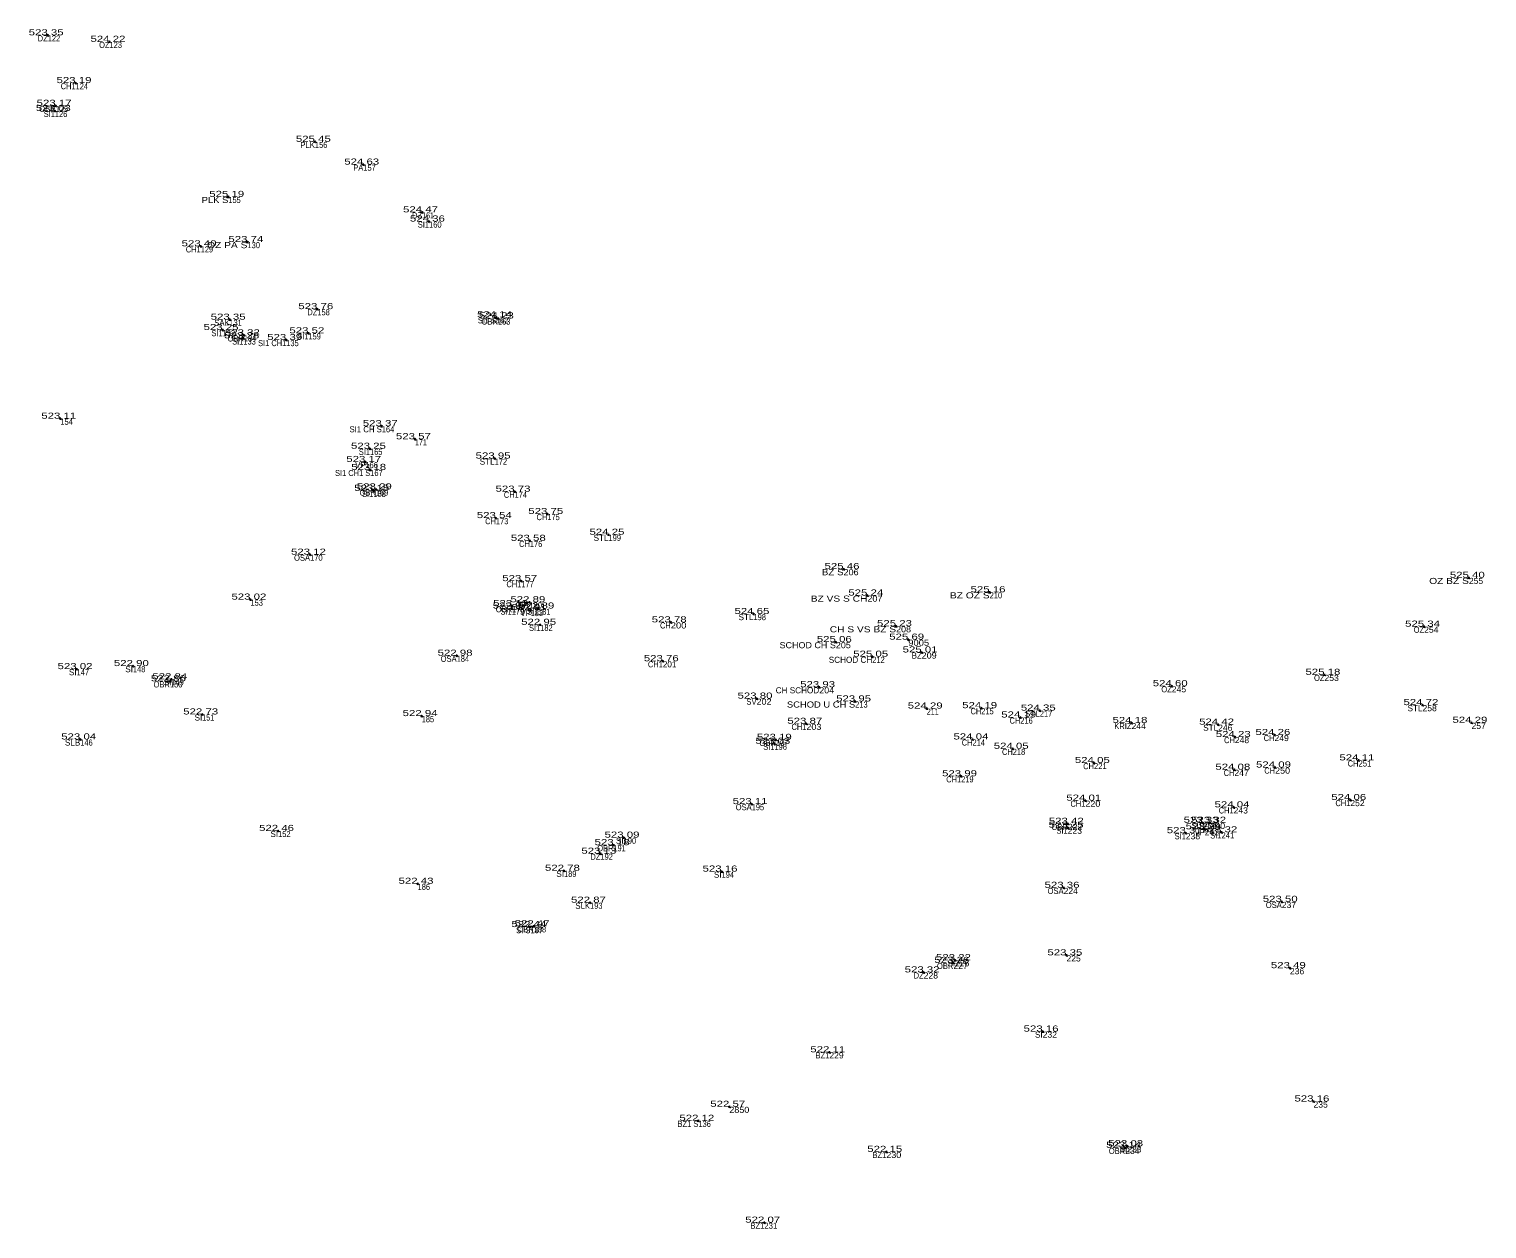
# Model space of a CAD drawing. Extents: x -643086 to -639283, y -1131805 to -1123269.
# Drawn here: x -641269.1 to -641197.4, y -1126078.8 to -1126019.7 of the extents above; entities that cross this region are included whole.
import ezdxf
from ezdxf.enums import TextEntityAlignment as Align

# ---------------------------------------------------------------- set-up
doc = ezdxf.new("R2010")
doc.units = 0
doc.header["$LTSCALE"] = 0.12
doc.header["$PDMODE"] = 32
doc.header["$PDSIZE"] = 0.06
for name, color, linetype in [('1', 7, 'Continuous'), ('2', 7, 'Continuous'), ('3', 7, 'Continuous'), ('4', 7, 'Continuous')]:
    doc.layers.add(name, color=color, linetype=linetype)

msp = doc.modelspace()

# ---------------------------------------------------------------- linework, layer by layer
at = {"layer": '1'}
for p in [(-641268.19, -1126020.04), (-641265.15, -1126020.36), (-641266.82, -1126022.39), (-641267.8, -1126023.51), (-641267.84, -1126023.76), (-641255.05, -1126025.28), (-641252.67, -1126026.4), (-641259.31, -1126027.99), (-641249.78, -1126028.75), (-641249.44, -1126029.2), (-641260.67, -1126030.42), (-641258.37, -1126030.21), (-641254.93, -1126033.51), (-641259.24, -1126034.03), (-641246.14, -1126033.91), (-641246.05, -1126033.97), (-641259.59, -1126034.54), (-641258.57, -1126034.95), (-641258.54, -1126034.8), (-641255.37, -1126034.7), (-641256.46, -1126035.03), (-641267.57, -1126038.9), (-641251.76, -1126039.27), (-641250.13, -1126039.91), (-641252.34, -1126040.38), (-641252.57, -1126041.03), (-641252.33, -1126041.42), (-641246.21, -1126040.86), (-641252.18, -1126042.45), (-641252.05, -1126042.38), (-641245.23, -1126042.49), (-641243.62, -1126043.59), (-641246.15, -1126043.79), (-641244.48, -1126044.91), (-641240.61, -1126044.61), (-641255.29, -1126045.59), (-641229.05, -1126046.3), (-641244.9, -1126046.89), (-641198.3, -1126046.73), (-641258.22, -1126047.8), (-641227.88, -1126047.6), (-641221.87, -1126047.44), (-641245.37, -1126048.24), (-641245.35, -1126048.12), (-641244.5, -1126047.93), (-641244.44, -1126048.31), (-641244.06, -1126048.24), (-641233.48, -1126048.51), (-641243.97, -1126049.04), (-641237.55, -1126048.92), (-641226.47, -1126049.11), (-641200.5, -1126049.13), (-641229.43, -1126049.89), (-641225.87, -1126049.77), (-641248.08, -1126050.56), (-641227.64, -1126050.61), (-641225.21, -1126050.4), (-641266.77, -1126051.22), (-641264, -1126051.07), (-641237.94, -1126050.83), (-641205.4, -1126051.5), (-641262.18, -1126051.82), (-641262.11, -1126051.72), (-641230.25, -1126052.11), (-641212.91, -1126052.06), (-641233.33, -1126052.67), (-641228.48, -1126052.81), (-641260.59, -1126053.45), (-641249.8, -1126053.53), (-641224.96, -1126053.16), (-641222.28, -1126053.14), (-641220.36, -1126053.6), (-641219.4, -1126053.26), (-641200.58, -1126052.99), (-641230.88, -1126053.91), (-641214.89, -1126053.87), (-641210.63, -1126053.95), (-641198.17, -1126053.86), (-641266.59, -1126054.68), (-641232.45, -1126054.89), (-641232.38, -1126054.7), (-641222.71, -1126054.68), (-641209.81, -1126054.56), (-641207.86, -1126054.46), (-641220.73, -1126055.14), (-641203.73, -1126055.71), (-641223.27, -1126056.49), (-641216.74, -1126055.84), (-641209.83, -1126056.17), (-641207.83, -1126056.06), (-641233.57, -1126057.86), (-641217.16, -1126057.69), (-641204.13, -1126057.66), (-641209.87, -1126058.02), (-641256.86, -1126059.18), (-641218.03, -1126059.02), (-641218.02, -1126058.83), (-641212.22, -1126059.29), (-641211.39, -1126058.78), (-641211.29, -1126059.1), (-641211.02, -1126058.78), (-641210.47, -1126059.25), (-641240.36, -1126059.88), (-641239.87, -1126059.51), (-641241.01, -1126060.3), (-641242.8, -1126061.14), (-641235.05, -1126061.18), (-641250, -1126061.78), (-641218.23, -1126061.98), (-641241.52, -1126062.71), (-641207.5, -1126062.67), (-641244.45, -1126063.91), (-641244.29, -1126063.87), (-641223.65, -1126065.67), (-641223.57, -1126065.54), (-641218.09, -1126065.3), (-641225.11, -1126066.14), (-641207.1, -1126065.93), (-641219.26, -1126069.05), (-641229.75, -1126070.07), (-641234.67, -1126072.75), (-641205.94, -1126072.49), (-641236.19, -1126073.44), (-641226.95, -1126074.97), (-641215.2, -1126074.77), (-641215.1, -1126074.69), (-641232.95, -1126078.45)]:
    msp.add_point(p, dxfattribs=at)

# ---------------------------------------------------------------- texts
at = {"layer": '2'}
for s, width, p in [('122', 0.8, (-641268.19, -1126020.34)), ('123', 0.8, (-641265.15, -1126020.66)), ('124', 0.8, (-641266.82, -1126022.69)), ('125', 0.8, (-641267.8, -1126023.81)), ('126', 0.8, (-641267.84, -1126024.06)), ('156', 0.8, (-641255.05, -1126025.58)), ('157', 0.8, (-641252.67, -1126026.7)), ('155', 0.8, (-641259.31, -1126028.29)), ('161', 0.7, (-641249.78, -1126029.05)), ('160', 0.85, (-641249.44, -1126029.5)), ('129', 0.8, (-641260.67, -1126030.72)), ('130', 0.85, (-641258.37, -1126030.51)), ('158', 0.8, (-641254.93, -1126033.81)), ('131', 0.7, (-641259.24, -1126034.33)), ('162', 0.8, (-641246.14, -1126034.21)), ('163', 0.8, (-641246.05, -1126034.27)), ('132', 0.8, (-641259.59, -1126034.84)), ('133', 0.8, (-641258.57, -1126035.25)), ('134', 0.8, (-641258.54, -1126035.1)), ('159', 0.8, (-641255.37, -1126035)), ('135', 0.8, (-641256.46, -1126035.33)), ('154', 0.8, (-641267.57, -1126039.2)), ('164', 0.8, (-641251.76, -1126039.57)), ('171', 0.7, (-641250.13, -1126040.21)), ('165', 0.8, (-641252.34, -1126040.68)), ('166', 0.85, (-641252.57, -1126041.33)), ('167', 0.8, (-641252.33, -1126041.72)), ('172', 0.8, (-641246.21, -1126041.16)), ('168', 0.8, (-641252.18, -1126042.75)), ('169', 0.8, (-641252.05, -1126042.68)), ('174', 0.8, (-641245.23, -1126042.79)), ('175', 0.8, (-641243.62, -1126043.89)), ('173', 0.8, (-641246.15, -1126044.09)), ('176', 0.8, (-641244.48, -1126045.21)), ('199', 0.8, (-641240.61, -1126044.91)), ('170', 0.85, (-641255.29, -1126045.89)), ('206', 1.1, (-641229.05, -1126046.6)), ('177', 0.8, (-641244.9, -1126047.19)), ('255', 1.05, (-641198.3, -1126047.03)), ('153', 0.8, (-641258.22, -1126048.1)), ('207', 1.1, (-641227.88, -1126047.9)), ('210', 0.85, (-641221.87, -1126047.74)), ('179', 0.8, (-641245.37, -1126048.54)), ('178', 0.8, (-641245.35, -1126048.42)), ('180', 0.85, (-641244.5, -1126048.23)), ('183', 0.8, (-641244.44, -1126048.61)), ('181', 0.7, (-641244.06, -1126048.54)), ('198', 0.8, (-641233.48, -1126048.81)), ('182', 0.8, (-641243.97, -1126049.34)), ('200', 1.15, (-641237.55, -1126049.22)), ('208', 1.1, (-641226.47, -1126049.41)), ('254', 1.05, (-641200.5, -1126049.43)), ('205', 1.1, (-641229.43, -1126050.19)), ('9005', 1.15, (-641225.87, -1126050.07)), ('184', 0.8, (-641248.08, -1126050.86)), ('212', 0.8, (-641227.64, -1126050.91)), ('209', 1.1, (-641225.21, -1126050.7)), ('147', 0.8, (-641266.77, -1126051.52)), ('148', 0.8, (-641264, -1126051.37)), ('150', 0.85, (-641262.18, -1126052.12)), ('149', 0.8, (-641262.11, -1126052.02)), ('204', 1.1, (-641230.25, -1126052.41)), ('245', 1.05, (-641212.91, -1126052.36)), ('253', 1.05, (-641205.4, -1126051.8)), ('202', 1.1, (-641233.33, -1126052.97)), ('213', 0.8, (-641228.48, -1126053.11)), ('151', 0.7, (-641260.59, -1126053.75)), ('185', 0.8, (-641249.8, -1126053.83)), ('211', 0.7, (-641224.96, -1126053.46)), ('215', 0.8, (-641222.28, -1126053.44)), ('216', 0.8, (-641220.36, -1126053.9)), ('217', 0.8, (-641219.4, -1126053.56)), ('258', 1.05, (-641200.58, -1126053.29)), ('203', 1.1, (-641230.88, -1126054.21)), ('244', 1.05, (-641214.89, -1126054.17)), ('246', 1.05, (-641210.63, -1126054.25)), ('257', 1.05, (-641198.17, -1126054.16)), ('146', 0.8, (-641266.59, -1126054.98)), ('196', 0.8, (-641232.45, -1126055.19)), ('197', 0.8, (-641232.38, -1126055)), ('214', 0.8, (-641222.71, -1126054.98)), ('248', 1.05, (-641209.81, -1126054.86)), ('249', 1.05, (-641207.86, -1126054.76)), ('218', 0.8, (-641220.73, -1126055.44)), ('251', 0.95, (-641203.73, -1126056.01)), ('219', 0.8, (-641223.27, -1126056.79)), ('221', 0.95, (-641216.74, -1126056.14)), ('247', 1.05, (-641209.83, -1126056.47)), ('250', 1.1, (-641207.83, -1126056.36)), ('195', 0.8, (-641233.57, -1126058.16)), ('220', 1.1, (-641217.16, -1126057.99)), ('252', 1.05, (-641204.13, -1126057.96)), ('243', 1.05, (-641209.87, -1126058.32)), ('152', 0.8, (-641256.86, -1126059.48)), ('223', 1.05, (-641218.03, -1126059.32)), ('222', 1.05, (-641218.02, -1126059.13)), ('238', 1.05, (-641212.22, -1126059.59)), ('239', 1.05, (-641211.39, -1126059.08)), ('242', 1.05, (-641211.29, -1126059.4)), ('240', 1.1, (-641211.02, -1126059.08)), ('241', 0.95, (-641210.47, -1126059.55)), ('191', 0.7, (-641240.36, -1126060.18)), ('190', 0.85, (-641239.87, -1126059.81)), ('192', 0.8, (-641241.01, -1126060.6)), ('189', 0.8, (-641242.8, -1126061.44)), ('194', 0.8, (-641235.05, -1126061.48)), ('186', 0.8, (-641250, -1126062.08)), ('224', 1.05, (-641218.23, -1126062.28)), ('193', 0.8, (-641241.52, -1126063.01)), ('237', 1.05, (-641207.5, -1126062.97)), ('187', 0.8, (-641244.45, -1126064.21)), ('188', 0.8, (-641244.29, -1126064.17)), ('227', 1.05, (-641223.65, -1126065.97)), ('226', 1.05, (-641223.57, -1126065.84)), ('225', 1.05, (-641218.09, -1126065.6)), ('228', 1.05, (-641225.11, -1126066.44)), ('236', 1.05, (-641207.1, -1126066.23)), ('232', 1.05, (-641219.26, -1126069.35)), ('229', 1.05, (-641229.75, -1126070.37)), ('2850', 1.1, (-641234.67, -1126073.05)), ('235', 1.05, (-641205.94, -1126072.79)), ('136', 0.8, (-641236.19, -1126073.74)), ('230', 1.1, (-641226.95, -1126075.27)), ('234', 1.05, (-641215.2, -1126075.07)), ('233', 1.05, (-641215.1, -1126074.99)), ('231', 0.95, (-641232.95, -1126078.75))]:
    msp.add_text(s, height=0.3, dxfattribs=dict(at, width=width)).set_placement(p)
msp.add_text('201', height=0.3, dxfattribs=at).set_placement((-641237.94, -1126051.13))
at = {"layer": '3', "width": 1.4}
for s, p in [('523 35 ', (-641268.19, -1126020.04)), ('524 22 ', (-641265.15, -1126020.36)), ('523 19 ', (-641266.82, -1126022.39)), ('523 03 ', (-641267.84, -1126023.76)), ('523 17 ', (-641267.8, -1126023.51)), ('525 45 ', (-641255.05, -1126025.28)), ('524 63 ', (-641252.67, -1126026.4)), ('525 19 ', (-641259.31, -1126027.99)), ('524 47 ', (-641249.78, -1126028.75)), ('524 36 ', (-641249.44, -1126029.2)), ('523 74 ', (-641258.37, -1126030.21)), ('523 40 ', (-641260.67, -1126030.42)), ('523 76 ', (-641254.93, -1126033.51)), ('523 25 ', (-641259.59, -1126034.54)), ('523 35 ', (-641259.24, -1126034.03)), ('524 14 ', (-641246.14, -1126033.91)), ('524 23 ', (-641246.05, -1126033.97)), ('523 28 ', (-641258.57, -1126034.95)), ('523 32 ', (-641258.54, -1126034.8)), ('523 39 ', (-641256.46, -1126035.03)), ('523 52 ', (-641255.37, -1126034.7)), ('523 11 ', (-641267.57, -1126038.9)), ('523 37 ', (-641251.76, -1126039.27)), ('523 57 ', (-641250.13, -1126039.91)), ('523 17 ', (-641252.57, -1126041.03)), ('523 25 ', (-641252.34, -1126040.38)), ('523 95 ', (-641246.21, -1126040.86)), ('523 18 ', (-641252.33, -1126041.42)), ('523 15 ', (-641252.18, -1126042.45)), ('523 29 ', (-641252.05, -1126042.38)), ('523 73 ', (-641245.23, -1126042.49)), ('523 54 ', (-641246.15, -1126043.79)), ('523 75 ', (-641243.62, -1126043.59)), ('524 25 ', (-641240.61, -1126044.61)), ('523 58 ', (-641244.48, -1126044.91)), ('523 12 ', (-641255.29, -1126045.59)), ('525 46 ', (-641229.05, -1126046.3)), ('525 40 ', (-641198.3, -1126046.73)), ('523 57 ', (-641244.9, -1126046.89)), ('525 16 ', (-641221.87, -1126047.44)), ('523 02 ', (-641258.22, -1126047.8)), ('523 12 ', (-641245.35, -1126048.12)), ('522 89 ', (-641244.5, -1126047.93)), ('525 24 ', (-641227.88, -1126047.6)), ('522 97 ', (-641245.37, -1126048.24)), ('522 91 ', (-641244.44, -1126048.31)), ('522 89 ', (-641244.06, -1126048.24)), ('524 65 ', (-641233.48, -1126048.51)), ('522 95 ', (-641243.97, -1126049.04)), ('523 78 ', (-641237.55, -1126048.92)), ('525 23 ', (-641226.47, -1126049.11)), ('525 34 ', (-641200.5, -1126049.13)), ('525 06 ', (-641229.43, -1126049.89)), ('525 69 ', (-641225.87, -1126049.77)), ('522 98 ', (-641248.08, -1126050.56)), ('523 76 ', (-641237.94, -1126050.83)), ('525 05 ', (-641227.64, -1126050.61)), ('525 01 ', (-641225.21, -1126050.4)), ('523 02 ', (-641266.77, -1126051.22)), ('522 90 ', (-641264, -1126051.07)), ('522 84 ', (-641262.11, -1126051.72)), ('525 18 ', (-641205.4, -1126051.5)), ('522 86 ', (-641262.18, -1126051.82)), ('523 93 ', (-641230.25, -1126052.11)), ('524 60 ', (-641212.91, -1126052.06)), ('523 80 ', (-641233.33, -1126052.67)), ('523 95 ', (-641228.48, -1126052.81)), ('524 29 ', (-641224.96, -1126053.16)), ('524 19 ', (-641222.28, -1126053.14)), ('524 72 ', (-641200.58, -1126052.99)), ('522 73 ', (-641260.59, -1126053.45)), ('522 94 ', (-641249.8, -1126053.53)), ('523 87 ', (-641230.88, -1126053.91)), ('524 19 ', (-641220.36, -1126053.6)), ('524 35 ', (-641219.4, -1126053.26)), ('524 18 ', (-641214.89, -1126053.87)), ('524 29 ', (-641198.17, -1126053.86)), ('524 42 ', (-641210.63, -1126053.95)), ('524 23 ', (-641209.81, -1126054.56)), ('524 26 ', (-641207.86, -1126054.46)), ('523 04 ', (-641266.59, -1126054.68)), ('523 03 ', (-641232.45, -1126054.89)), ('523 19 ', (-641232.38, -1126054.7)), ('524 04 ', (-641222.71, -1126054.68)), ('524 05 ', (-641220.73, -1126055.14)), ('524 05 ', (-641216.74, -1126055.84)), ('524 09 ', (-641207.83, -1126056.06)), ('524 11 ', (-641203.73, -1126055.71)), ('523 99 ', (-641223.27, -1126056.49)), ('524 08 ', (-641209.83, -1126056.17)), ('523 11 ', (-641233.57, -1126057.86)), ('524 01 ', (-641217.16, -1126057.69)), ('524 04 ', (-641209.87, -1126058.02)), ('524 06 ', (-641204.13, -1126057.66)), ('523 42 ', (-641218.02, -1126058.83)), ('523 33 ', (-641211.39, -1126058.78)), ('523 32 ', (-641211.02, -1126058.78)), ('522 46 ', (-641256.86, -1126059.18)), ('523 09 ', (-641239.87, -1126059.51)), ('523 25 ', (-641218.03, -1126059.02)), ('523 31 ', (-641212.22, -1126059.29)), ('523 29 ', (-641211.29, -1126059.1)), ('523 32 ', (-641210.47, -1126059.25)), ('523 13 ', (-641241.01, -1126060.3)), ('523 18 ', (-641240.36, -1126059.88)), ('522 43 ', (-641250, -1126061.78)), ('522 78 ', (-641242.8, -1126061.14)), ('523 16 ', (-641235.05, -1126061.18)), ('523 36 ', (-641218.23, -1126061.98)), ('522 87 ', (-641241.52, -1126062.71)), ('523 50 ', (-641207.5, -1126062.67)), ('522 44 ', (-641244.45, -1126063.91)), ('522 47 ', (-641244.29, -1126063.87)), ('523 35 ', (-641218.09, -1126065.3)), ('523 26 ', (-641223.65, -1126065.67)), ('523 22 ', (-641223.57, -1126065.54)), ('523 49 ', (-641207.1, -1126065.93)), ('523 32 ', (-641225.11, -1126066.14)), ('523 16 ', (-641219.26, -1126069.05)), ('522 11 ', (-641229.75, -1126070.07)), ('523 16 ', (-641205.94, -1126072.49)), ('522 57 ', (-641234.67, -1126072.75)), ('522 12 ', (-641236.19, -1126073.44)), ('523 03 ', (-641215.1, -1126074.69)), ('522 15 ', (-641226.95, -1126074.97)), ('523 14 ', (-641215.2, -1126074.77)), ('522 07 ', (-641232.95, -1126078.45))]:
    msp.add_text(s, height=0.3, dxfattribs=at).set_placement(p, align=Align.CENTER)
at = {"layer": '4'}
for s, width, p in [('DZ', 0.9, (-641268.19, -1126020.34)), ('OZ', 0.85, (-641265.15, -1126020.66)), ('CH1', 0.8, (-641266.82, -1126022.69)), ('OBR', 0.9, (-641267.8, -1126023.81)), ('SI1', 0.8, (-641267.84, -1126024.06)), ('PLK', 0.95, (-641255.05, -1126025.58)), ('PA', 0.9, (-641252.67, -1126026.7)), ('PLK S', 1.15, (-641259.31, -1126028.29)), ('DZ', 0.9, (-641249.78, -1126029.05)), ('SI1', 0.8, (-641249.44, -1126029.5)), ('CH1', 0.8, (-641260.67, -1126030.72)), ('OZ PA S', 1.25, (-641258.37, -1126030.51)), ('DZ', 0.9, (-641254.93, -1126033.81)), ('SAK', 0.95, (-641259.24, -1126034.33)), ('SI1 S', 0.8, (-641246.14, -1126034.21)), ('OBR', 0.9, (-641246.05, -1126034.27)), ('SI1', 0.8, (-641259.59, -1126034.84)), ('OBR', 0.9, (-641258.54, -1126035.1)), ('SI1', 0.8, (-641258.57, -1126035.25)), ('SI1', 0.8, (-641255.37, -1126035)), ('SI1 CH1', 0.8, (-641256.46, -1126035.33)), ('SI1 CH S', 0.95, (-641251.76, -1126039.57)), ('SI1', 0.8, (-641252.34, -1126040.68)), ('SI1 CH1 S', 0.8, (-641252.33, -1126041.72)), ('VP', 0.9, (-641252.57, -1126041.33)), ('OBR', 0.9, (-641252.05, -1126042.68)), ('SI1', 0.8, (-641252.18, -1126042.75)), ('CH', 0.8, (-641245.23, -1126042.79)), ('CH', 0.8, (-641243.62, -1126043.89)), ('CH', 0.8, (-641246.15, -1126044.09)), ('CH', 0.8, (-641244.48, -1126045.21)), ('OSA', 0.9, (-641255.29, -1126045.89)), ('BZ S', 1.2, (-641229.05, -1126046.6)), ('CH1', 0.8, (-641244.9, -1126047.19)), ('OZ BZ S', 1.25, (-641198.3, -1126047.03)), ('BZ VS S CH', 1.25, (-641227.88, -1126047.9)), ('BZ OZ S', 1.25, (-641221.87, -1126047.74)), ('OBR', 0.9, (-641245.35, -1126048.42)), ('SI1', 0.8, (-641245.37, -1126048.54)), ('SI1', 0.8, (-641244.5, -1126048.23)), ('VP', 0.9, (-641244.44, -1126048.61)), ('SI1', 0.8, (-641244.06, -1126048.54)), ('SI1', 0.8, (-641243.97, -1126049.34)), ('CH', 0.8, (-641237.55, -1126049.22)), ('CH S VS BZ S', 1.25, (-641226.47, -1126049.41)), ('OZ', 0.85, (-641200.5, -1126049.43)), ('SCHOD CH S', 1.1, (-641229.43, -1126050.19)), ('OSA', 0.9, (-641248.08, -1126050.86)), ('BZ', 0.95, (-641225.21, -1126050.7)), ('CH1', 0.8, (-641237.94, -1126051.13)), ('OBR', 0.9, (-641262.18, -1126052.12)), ('OZ', 0.85, (-641212.91, -1126052.36)), ('OZ', 0.85, (-641205.4, -1126051.8)), ('SV', 0.9, (-641233.33, -1126052.97)), ('SCHOD U CH S', 1.15, (-641228.48, -1126053.11)), ('CH', 0.8, (-641222.28, -1126053.44)), ('CH', 0.8, (-641220.36, -1126053.9)), ('CH1', 0.8, (-641230.88, -1126054.21)), ('KRIZ', 0.9, (-641214.89, -1126054.17)), ('OBR', 0.9, (-641232.38, -1126055)), ('SI1', 0.8, (-641232.45, -1126055.19)), ('CH', 0.8, (-641222.71, -1126054.98)), ('CH', 0.8, (-641209.81, -1126054.86)), ('CH', 0.8, (-641207.86, -1126054.76)), ('CH', 0.8, (-641220.73, -1126055.44)), ('CH', 0.8, (-641203.73, -1126056.01)), ('CH1', 0.8, (-641223.27, -1126056.79)), ('CH', 0.8, (-641216.74, -1126056.14)), ('CH', 0.8, (-641209.83, -1126056.47)), ('CH', 0.8, (-641207.83, -1126056.36)), ('OSA', 0.9, (-641233.57, -1126058.16)), ('CH1', 0.8, (-641217.16, -1126057.99)), ('CH1', 0.8, (-641204.13, -1126057.96)), ('CH1', 0.8, (-641209.87, -1126058.32)), ('OBR', 0.9, (-641218.02, -1126059.13)), ('SI1', 0.8, (-641218.03, -1126059.32)), ('SI1', 0.8, (-641212.22, -1126059.59)), ('SI1', 0.8, (-641211.39, -1126059.08)), ('VP', 0.9, (-641211.29, -1126059.4)), ('SI1', 0.8, (-641211.02, -1126059.08)), ('SI1', 0.8, (-641210.47, -1126059.55)), ('OBR', 0.9, (-641240.36, -1126060.18)), ('DZ', 0.9, (-641241.01, -1126060.6)), ('OSA', 0.9, (-641218.23, -1126062.28)), ('SLK', 0.95, (-641241.52, -1126063.01)), ('OSA', 0.9, (-641207.5, -1126062.97)), ('SI S', 0.9, (-641244.45, -1126064.21)), ('OBR', 0.9, (-641244.29, -1126064.17)), ('OBR', 0.9, (-641223.65, -1126065.97)), ('DZ', 0.9, (-641225.11, -1126066.44)), ('BZ1', 0.9, (-641229.75, -1126070.37)), ('BZ1 S', 0.85, (-641236.19, -1126073.74)), ('BZ1', 0.9, (-641226.95, -1126075.27)), ('OBR', 0.9, (-641215.2, -1126075.07)), ('BZ1', 0.9, (-641232.95, -1126078.75))]:
    msp.add_text(s, height=0.3, dxfattribs=dict(at, width=width)).set_placement(p, align=Align.RIGHT)
for s, p in [('STL', (-641246.21, -1126041.16)), ('STL', (-641240.61, -1126044.91)), ('STL', (-641233.48, -1126048.81)), ('SCHOD CH', (-641227.64, -1126050.91)), ('SI', (-641266.77, -1126051.52)), ('SI', (-641264, -1126051.37)), ('SI', (-641262.11, -1126052.02)), ('CH SCHOD', (-641230.25, -1126052.41)), ('SI', (-641260.59, -1126053.75)), ('STL', (-641219.4, -1126053.56)), ('STL', (-641200.58, -1126053.29)), ('STL', (-641210.63, -1126054.25)), ('SLB', (-641266.59, -1126054.98)), ('SI', (-641256.86, -1126059.48)), ('SI', (-641239.87, -1126059.81)), ('SI', (-641242.8, -1126061.44)), ('SI', (-641235.05, -1126061.48)), ('SI', (-641223.57, -1126065.84)), ('SI', (-641219.26, -1126069.35)), ('SI', (-641215.1, -1126074.99))]:
    msp.add_text(s, height=0.3, dxfattribs=at).set_placement(p, align=Align.RIGHT)

doc.saveas('drawing.dxf')
